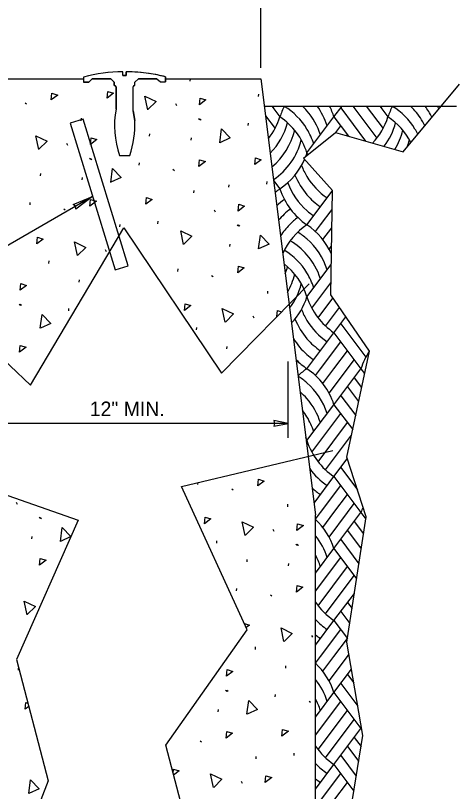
# Model space of a CAD drawing. Extents: x 99862 to 103151, y 100000 to 102076.
# Drawn here: x 102002 to 102490, y 100427 to 101282 of the extents above; entities that cross this region are included whole.
import ezdxf

# ---------------------------------------------------------------- set-up
doc = ezdxf.new("R2010")
doc.units = 0
for name, color, linetype in [('Level 15', 7, 'Continuous'), ('Level 17', 7, 'Continuous'), ('Level 20', 7, 'Continuous'), ('Level 24', 7, 'Continuous'), ('Level 25', 7, 'Continuous'), ('Level 26', 7, 'Continuous'), ('Level 6', 7, 'Continuous')]:
    doc.layers.add(name, color=color, linetype=linetype)

msp = doc.modelspace()

# ---------------------------------------------------------------- linework, layer by layer
at = {"layer": 'Level 15'}
for p, q in [((102272.15, 101223.92), (102272.15, 101307.93)), ((102087, 101082.43), (101858.43, 100950.47)), ((102302.15, 100816.59), (102302.15, 100900.59)), ((102302.15, 100832.59), (101942.15, 100832.59))]:
    msp.add_line(p, q, dxfattribs=at)
for points in [[(102087, 101082.43), (102068.72, 101068.43), (102068.15, 101071.55), (102065.74, 101073.6)], [(102302.15, 100832.59), (102286.43, 100835.67), (102287.16, 100832.59), (102286.43, 100829.5)]]:
    msp.add_lwpolyline(points, close=True, dxfattribs=at)
at = {"layer": 'Level 17'}
for p, q in [((101972.15, 101211.92), (102077.18, 101211.92)), ((102167.18, 101211.92), (102272.15, 101211.92)), ((102272.15, 101211.92), (102332.15, 100731.92)), ((102275.9, 101181.92), (102487.15, 101181.92)), ((102332.15, 100221.92), (102332.15, 100731.92))]:
    msp.add_line(p, q, dxfattribs=at)
at = {"layer": 'Level 24'}
for points in [[(102332.15, 100221.92), (102387.82, 100276.55), (102364.81, 100368.6), (102384.28, 100488.98), (102366.58, 100591.66), (102387.82, 100729.74), (102366.58, 100795.24), (102391.36, 100912.08), (102348.89, 100974.04), (102350.66, 101089.11), (102318.8, 101124.51), (102354.19, 101152.84), (102428.52, 101131.6), (102490.46, 101205.95)], [(101928.81, 100959.96), (102018.56, 100874.55), (102121.42, 101047.85), (102228.7, 100887.69), (102325.01, 100986.24)], [(101902.53, 100785.04), (102071.08, 100725.91), (102003.22, 100572.61), (102038.24, 100439.01), (102007.6, 100360.17), (102200.23, 100353.6), (102167.39, 100478.43), (102257.14, 100605.46), (102184.9, 100763.14), (102351.26, 100802.56)]]:
    msp.add_lwpolyline(points, dxfattribs=at)
at = {"layer": 'Level 25'}
for p, q in [((102284.1, 101181.92), (102293.07, 101169.97)), ((102352.46, 101169.97), (102361.43, 101181.92)), ((102359.89, 101179.87), (102387.24, 101143.39)), ((102373.2, 101181.92), (102399.63, 101146.68)), ((102388.04, 101181.92), (102406.51, 101157.3)), ((102402.89, 101181.92), (102411.86, 101169.97)), ((102277.23, 101171.28), (102287.72, 101157.3)), ((102322.77, 101130.37), (102352.46, 101169.97)), ((102352.46, 101169.97), (102368.34, 101148.79)), ((102354.42, 101152.78), (102359.89, 101160.07)), ((102280.2, 101147.52), (102280.83, 101146.68)), ((102366.65, 101149.28), (102367.31, 101150.17)), ((102286.14, 101100.01), (102293.07, 101090.77)), ((102322.77, 101051.17), (102350.64, 101088.35)), ((102337.61, 101051.17), (102350.33, 101068.13)), ((102332.07, 101043.79), (102337.61, 101051.17)), ((102340.23, 101034.86), (102350.02, 101047.92)), ((102347.12, 101024.24), (102349.71, 101027.71)), ((102322.77, 100971.98), (102349.4, 101007.49)), ((102328.11, 100959.31), (102349.09, 100987.28)), ((102335, 100948.69), (102351.33, 100970.47)), ((102343.16, 100939.77), (102358.42, 100960.13)), ((102352.46, 100932.38), (102365.51, 100949.78)), ((102359.89, 100942.28), (102387.51, 100905.45)), ((102322.77, 100892.78), (102352.46, 100932.38)), ((102352.46, 100932.38), (102382.16, 100892.78)), ((102337.61, 100892.78), (102359.89, 100922.48)), ((102352.46, 100892.78), (102367.31, 100912.58)), ((102367.31, 100892.78), (102374.74, 100902.68)), ((102332.07, 100885.39), (102337.61, 100892.78)), ((102340.23, 100876.47), (102352.46, 100892.78)), ((102347.12, 100865.85), (102367.31, 100892.78)), ((102352.46, 100853.18), (102382.16, 100892.78)), ((102382.16, 100892.78), (102386.14, 100887.48)), ((102374.74, 100882.88), (102382.87, 100872.04)), ((102367.31, 100872.98), (102379.6, 100856.61)), ((102359.89, 100863.08), (102376.32, 100841.17)), ((102322.77, 100813.59), (102352.46, 100853.18)), ((102352.46, 100853.18), (102373.05, 100825.74)), ((102328.11, 100800.92), (102359.89, 100843.29)), ((102335, 100790.3), (102367.31, 100833.39)), ((102343.16, 100781.38), (102371.72, 100819.46)), ((102352.46, 100773.99), (102367.13, 100793.55)), ((102359.89, 100783.89), (102378.16, 100759.52)), ((102330.55, 100744.77), (102352.46, 100773.99)), ((102352.46, 100773.99), (102382.16, 100734.39)), ((102337.61, 100734.39), (102359.89, 100764.09)), ((102352.46, 100734.39), (102367.31, 100754.19)), ((102367.31, 100734.39), (102374.74, 100744.29)), ((102332.15, 100727.11), (102337.61, 100734.39)), ((102340.23, 100718.08), (102352.46, 100734.39)), ((102347.12, 100707.46), (102367.31, 100734.39)), ((102352.46, 100694.79), (102382.16, 100734.39)), ((102382.16, 100734.39), (102387.45, 100727.34)), ((102374.74, 100724.49), (102384.92, 100710.91)), ((102367.31, 100714.59), (102382.4, 100694.48)), ((102359.89, 100704.69), (102379.87, 100678.05)), ((102332.15, 100667.71), (102352.46, 100694.79)), ((102352.46, 100694.79), (102377.34, 100661.62)), ((102332.15, 100647.91), (102359.89, 100684.89)), ((102335, 100631.91), (102367.31, 100674.99)), ((102343.16, 100622.98), (102374.74, 100665.09)), ((102352.46, 100615.6), (102374.86, 100645.45)), ((102374.74, 100645.3), (102374.82, 100645.19)), ((102367.31, 100635.4), (102372.29, 100628.76)), ((102359.89, 100625.5), (102369.76, 100612.33)), ((102332.15, 100588.52), (102352.46, 100615.6)), ((102352.46, 100615.6), (102367.24, 100595.9)), ((102337.61, 100576), (102359.89, 100605.7)), ((102352.46, 100576), (102367.2, 100595.64)), ((102332.15, 100568.72), (102337.61, 100576)), ((102340.23, 100559.68), (102352.46, 100576)), ((102347.12, 100549.07), (102367.31, 100576)), ((102367.31, 100576), (102368.91, 100578.13)), ((102352.46, 100536.4), (102371.69, 100562.03)), ((102367.31, 100556.2), (102374.3, 100546.88)), ((102359.89, 100546.3), (102378.73, 100521.18)), ((102332.15, 100509.32), (102352.46, 100536.4)), ((102352.46, 100536.4), (102382.16, 100496.8)), ((102332.15, 100489.52), (102359.89, 100526.5)), ((102335, 100473.52), (102367.31, 100516.6)), ((102343.16, 100464.59), (102374.74, 100506.7)), ((102352.46, 100457.2), (102382.16, 100496.8)), ((102382.16, 100496.8), (102383.16, 100495.47)), ((102374.74, 100486.9), (102382.31, 100476.81)), ((102367.31, 100477), (102379.68, 100460.52)), ((102359.89, 100467.1), (102377.04, 100444.23)), ((102332.15, 100430.12), (102352.46, 100457.2)), ((102352.46, 100457.2), (102374.41, 100427.94)), ((102337.61, 100417.61), (102359.89, 100447.31)), ((102352.46, 100417.61), (102367.31, 100437.41))]:
    msp.add_line(p, q, dxfattribs=at)
for centre, start, end in [((102357.26, 101157.09), 160.70359, 162.3566), ((102364.69, 101147.19), 152.47235, 162.3566), ((102258.57, 101117.49), 31.33163, 58.48737), ((102266, 101127.39), 40.94134, 46.52039), ((102273.42, 101137.29), 17.6434, 36.43411), ((102280.84, 101147.19), 17.6434, 27.52765), ((102476.06, 101157.09), 160.70359, 162.3566), ((102483.48, 101147.19), 152.47235, 162.3566), ((102377.36, 101117.49), 31.33163, 58.48737), ((102384.79, 101127.39), 40.94134, 46.52039), ((102392.21, 101137.29), 25.38723, 36.43411), ((102399.64, 101147.19), 24.85547, 27.52765), ((102221.45, 101192.75), 321.64092, 342.3566), ((102251.15, 101107.59), 17.6434, 56.09639), ((102265.99, 101127.39), 17.6434, 40.94141), ((102340.24, 101192.75), 316.69133, 342.3566), ((102369.94, 101107.59), 26.97043, 56.09639), ((102384.79, 101127.39), 25.91673, 40.94141), ((102228.87, 101182.85), 315.39859, 345.01126), ((102347.67, 101182.85), 322.94626, 345.01126), ((102236.3, 101172.95), 309.65405, 346.31988), ((102258.57, 101117.49), 17.6434, 31.33172), ((102355.09, 101172.95), 328.94693, 346.31988), ((102377.36, 101117.49), 26.44403, 31.33172), ((102243.72, 101163.05), 304.25669, 345.77133), ((102362.52, 101163.05), 339.69661, 345.77133), ((102251.15, 101153.15), 339.35954, 342.3566), ((102394.39, 101153.15), 197.64354, 199.34519), ((102251.15, 101153.15), 303.90361, 336.45662), ((102386.96, 101143.25), 200.87781, 211.33197), ((102379.54, 101133.35), 201.43438, 220.94161), ((102386.96, 101143.25), 211.33188, 236.09639), ((102372.11, 101123.45), 200.24322, 228.95992), ((102334.99, 101028.4), 123.90361, 128.91055), ((102364.69, 101113.55), 197.6434, 236.09639), ((102379.54, 101133.35), 220.94154, 236.09639), ((102342.41, 101018.5), 126.30625, 134.60118), ((102349.84, 101008.6), 127.1006, 140.76474), ((102357.26, 100998.7), 126.331, 135.71278), ((102372.11, 101123.45), 228.95986, 236.09639), ((102357.26, 100998.7), 135.71269, 147.64184), ((102364.69, 100988.8), 123.90361, 155.71959), ((102280.84, 100988.8), 23.85276, 56.09634), ((102273.42, 100978.9), 48.95968, 58.54646), ((102266, 100969), 40.94134, 59.30215), ((102273.42, 100978.9), 17.6434, 48.95975), ((102258.57, 100959.1), 31.33163, 58.48737), ((102265.99, 100969), 17.6434, 40.94141), ((102251.15, 100949.2), 17.6434, 51.81332), ((102228.87, 101024.46), 338.86712, 345.01126), ((102236.3, 101014.56), 330.17264, 346.31988), ((102258.57, 100959.1), 17.6434, 31.33172), ((102243.72, 101004.66), 322.96898, 345.77133), ((102251.15, 100994.76), 316.60104, 342.3566), ((102394.39, 100994.76), 197.64354, 236.09639), ((102386.96, 100984.86), 200.87781, 211.33197), ((102379.54, 100974.96), 201.43438, 220.94161), ((102386.96, 100984.86), 211.33188, 236.09639), ((102372.11, 100965.06), 211.29269, 228.95992), ((102379.54, 100974.96), 220.94154, 236.09639), ((102372.11, 100965.06), 228.95986, 236.09639), ((102453.78, 100870), 146.25564, 162.3566), ((102364.69, 100955.16), 224.18689, 236.09639), ((102357.26, 100840.31), 126.331, 127.8157), ((102364.69, 100830.41), 123.90361, 133.43069), ((102280.84, 100830.41), 17.6434, 56.09634), ((102273.42, 100820.51), 48.95968, 58.12998), ((102273.42, 100820.51), 17.6434, 48.95975), ((102266, 100810.61), 40.94134, 49.08438), ((102265.99, 100810.61), 17.6434, 40.94141), ((102258.57, 100800.71), 31.33163, 38.03389), ((102258.57, 100800.71), 17.6434, 31.33172), ((102251.15, 100790.81), 17.6434, 20.62953), ((102251.15, 100836.37), 340.91273, 342.3566), ((102394.39, 100836.37), 197.64354, 236.09639), ((102386.96, 100826.47), 215.5249, 236.09639), ((102379.54, 100816.57), 227.19281, 236.09639), ((102453.78, 100711.61), 157.47358, 162.3566), ((102280.84, 100672.01), 17.6434, 46.94368), ((102273.42, 100662.11), 17.6434, 38.60116), ((102265.99, 100652.21), 17.6434, 28.32156), ((102394.39, 100677.97), 214.10189, 236.09639), ((102386.96, 100668.07), 223.17637, 236.09639), ((102379.54, 100658.17), 230.91594, 236.09639), ((102280.84, 100513.62), 17.6434, 46.94368), ((102273.42, 100503.72), 17.6434, 38.60116), ((102265.99, 100493.82), 17.6434, 28.32156), ((102340.24, 100559.18), 303.90361, 304.53819), ((102394.39, 100519.58), 214.10189, 236.09639), ((102386.96, 100509.68), 223.17637, 236.09639), ((102379.54, 100499.78), 230.91594, 236.09639)]:
    msp.add_arc(centre, 75.15, start, end, dxfattribs=at)
at = {"layer": 'Level 26'}
for p, q in [((102194.45, 101209.4), (102194.62, 101211.92)), ((102269.59, 101192.23), (102269.77, 101194.85)), ((102012.89, 101185.55), (102014.44, 101184.42)), ((102178.13, 101184.71), (102179.2, 101182.55)), ((102074.53, 101165.75), (102074.71, 101168.37)), ((102203.49, 101168.18), (102205.04, 101167.04)), ((102204.7, 101167.97), (102206.25, 101166.83)), ((102258.16, 101160.54), (102258.34, 101163.16)), ((102149.67, 101148.59), (102149.85, 101151.21)), ((102195.48, 101144.24), (102195.66, 101146.86)), ((102058.21, 101141.06), (102059.28, 101138.9)), ((102083.58, 101124.53), (102085.13, 101123.39)), ((102084.79, 101124.33), (102086.34, 101123.19)), ((102138.24, 101116.89), (102138.42, 101119.51)), ((102175.37, 101112.26), (102176.91, 101111.12)), ((102029.75, 101104.94), (102029.94, 101107.56)), ((102075.56, 101100.6), (102075.74, 101103.22)), ((102237.01, 101092.46), (102237.19, 101095.07)), ((102278.8, 101096.04), (102278.98, 101098.66)), ((102198.37, 101086.49), (102198.55, 101089.11)), ((102018.33, 101073.25), (102018.51, 101075.86)), ((102055.45, 101068.62), (102057, 101067.48)), ((102220.69, 101067.77), (102221.76, 101065.61)), ((102117.1, 101048.81), (102117.28, 101051.43)), ((102158.88, 101052.4), (102159.06, 101055.01)), ((102246.06, 101051.24), (102247.61, 101050.1)), ((102247.27, 101051.03), (102248.82, 101049.89)), ((102238.04, 101027.31), (102238.22, 101029.92)), ((102100.77, 101024.12), (102101.84, 101021.96)), ((102038.97, 101008.75), (102039.15, 101011.37)), ((102180.81, 100999.95), (102180.99, 101002.57)), ((102072.32, 100988), (102072.5, 100990.62)), ((102217.93, 100995.32), (102219.48, 100994.18)), ((102279.57, 100975.52), (102279.76, 100978.13)), ((102006.22, 100963.95), (102007.77, 100962.81)), ((102007.43, 100963.74), (102008.98, 100962.6)), ((102060.89, 100956.31), (102061.07, 100958.93)), ((102263.25, 100950.83), (102264.32, 100948.67)), ((102201.45, 100935.46), (102201.63, 100938.07)), ((102234.8, 100914.71), (102234.98, 100917.33)), ((102202.83, 100765.32), (102202.98, 100767.42)), ((102239.96, 100760.69), (102241.51, 100759.55)), ((102002.89, 100745.85), (102003.96, 100743.68)), ((102301.6, 100740.88), (102301.79, 100743.5)), ((102028.25, 100729.31), (102029.8, 100728.18)), ((102029.46, 100729.11), (102031.01, 100727.97)), ((102285.28, 100716.2), (102286.35, 100714.04)), ((102020.24, 100705.38), (102020.42, 100708)), ((102223.47, 100700.82), (102223.66, 100703.44)), ((102310.65, 100699.67), (102312.2, 100698.53)), ((102311.86, 100699.46), (102313.41, 100698.32)), ((102256.82, 100680.08), (102257.01, 100682.69)), ((102302.63, 100675.73), (102302.81, 100678.35)), ((102245.4, 100648.38), (102245.58, 100651)), ((102282.52, 100643.75), (102284.07, 100642.61)), ((102327.84, 100599.26), (102328.91, 100597.1)), ((102266.04, 100583.88), (102266.22, 100586.5)), ((102005.56, 100561.09), (102005.7, 100563.13)), ((102299.39, 100563.14), (102299.57, 100565.75)), ((102233.3, 100539.08), (102234.84, 100537.94)), ((102234.5, 100538.88), (102236.05, 100537.74)), ((102287.96, 100531.44), (102288.14, 100534.06)), ((102325.08, 100526.81), (102326.63, 100525.67)), ((102225.28, 100515.15), (102225.46, 100517.77)), ((102205.17, 100483.16), (102206.71, 100482.03)), ((102308.6, 100466.94), (102308.78, 100469.56)), ((102266.81, 100463.36), (102266.99, 100465.98)), ((102250.49, 100438.67), (102251.56, 100436.51))]:
    msp.add_line(p, q, dxfattribs=at)
for points in [[(102041.54, 101188.61), (102042.27, 101195.96), (102048.64, 101194.03), (102041.54, 101188.61)], [(102102.93, 101190.69), (102103.66, 101198.04), (102110.03, 101196.11), (102102.93, 101190.69)], [(102147.72, 101177.83), (102144.5, 101192.86), (102156.83, 101186.87), (102147.92, 101178)], [(102204.52, 101183.29), (102205.24, 101190.64), (102211.62, 101188.71), (102204.52, 101183.29)], [(102226.82, 101141.48), (102228.94, 101156.71), (102238.48, 101146.86), (102227.07, 101141.57)], [(102027.8, 101134.18), (102024.58, 101149.21), (102036.91, 101143.22), (102028.01, 101134.35)], [(102084.6, 101139.65), (102085.33, 101147), (102091.7, 101145.07), (102084.6, 101139.65)], [(102204.02, 101115.32), (102204.75, 101122.67), (102211.12, 101120.74), (102204.02, 101115.32)], [(102265.41, 101117.4), (102266.14, 101124.75), (102272.51, 101122.82), (102265.41, 101117.4)], [(102106.91, 101097.83), (102109.02, 101113.06), (102118.56, 101103.21), (102107.16, 101097.92)], [(102084.1, 101071.67), (102084.83, 101079.03), (102091.2, 101077.09), (102084.1, 101071.67)], [(102145.5, 101073.75), (102146.22, 101081.1), (102152.59, 101079.17), (102145.5, 101073.75)], [(102247.08, 101066.35), (102247.81, 101073.71), (102254.18, 101071.77), (102247.08, 101066.35)], [(102187.11, 101029.6), (102183.89, 101044.63), (102196.23, 101038.64), (102187.32, 101029.77)], [(102025.58, 101030.11), (102026.3, 101037.46), (102032.68, 101035.52), (102025.58, 101030.11)], [(102269.39, 101024.54), (102271.5, 101039.77), (102281.04, 101029.92), (102269.64, 101024.63)], [(102070.36, 101017.24), (102067.14, 101032.28), (102079.48, 101026.28), (102070.57, 101017.42)], [(102246.58, 100998.38), (102247.31, 101005.73), (102253.68, 101003.8), (102246.58, 100998.38)], [(102007.25, 100979.06), (102007.97, 100986.41), (102014.35, 100984.48), (102007.25, 100979.06)], [(102188.06, 100956.81), (102188.78, 100964.16), (102195.16, 100962.23), (102188.06, 100956.81)], [(102232.84, 100943.95), (102229.62, 100958.98), (102241.95, 100952.99), (102233.05, 100944.12)], [(102289.71, 100950.12), (102290.37, 100956.77), (102294.87, 100955.4)], [(102029.55, 100937.25), (102031.67, 100952.48), (102041.21, 100942.62), (102029.8, 100937.34)], [(102006.75, 100911.09), (102007.48, 100918.44), (102013.85, 100916.51), (102006.75, 100911.09)], [(102268.61, 100763.75), (102269.34, 100771.1), (102275.71, 100769.17), (102268.61, 100763.75)], [(102210.09, 100722.18), (102210.81, 100729.53), (102217.19, 100727.6), (102210.09, 100722.18)], [(102051.58, 100702.62), (102053.69, 100717.84), (102063.17, 100708.05)], [(102254.87, 100709.32), (102251.65, 100724.35), (102263.98, 100718.35), (102255.08, 100709.49)], [(102311.67, 100714.78), (102312.4, 100722.13), (102318.77, 100720.2), (102311.67, 100714.78)], [(102063.12, 100707.94), (102051.83, 100702.71)], [(102028.78, 100676.45), (102029.51, 100683.81), (102035.88, 100681.87), (102028.78, 100676.45)], [(102311.18, 100646.81), (102311.9, 100654.16), (102318.27, 100652.23), (102311.18, 100646.81)], [(102015.04, 100622.03), (102011.82, 100637.06), (102024.15, 100631.06), (102015.24, 100622.2)], [(102253.95, 100612.42), (102259.75, 100610.66), (102256.05, 100607.84)], [(102297.44, 100592.38), (102294.21, 100607.41), (102306.55, 100601.41), (102297.64, 100592.55)], [(102234.32, 100554.2), (102235.04, 100561.55), (102241.42, 100559.61), (102234.32, 100554.2)], [(102012.82, 100517.95), (102013.54, 100525.3), (102015.8, 100524.62)], [(102016.76, 100520.96), (102012.82, 100517.95)], [(102256.62, 100512.38), (102258.74, 100527.61), (102268.28, 100517.76), (102256.87, 100512.47)], [(102295.21, 100488.3), (102295.94, 100495.65), (102302.31, 100493.72), (102295.21, 100488.3)], [(102233.82, 100486.22), (102234.55, 100493.57), (102240.92, 100491.64), (102233.82, 100486.22)], [(102175.56, 100447.37), (102176.02, 100452.01), (102182.39, 100450.07), (102176.11, 100445.28)], [(102220.08, 100431.79), (102216.86, 100446.82), (102229.19, 100440.83), (102220.28, 100431.96)], [(102276.88, 100437.26), (102277.61, 100444.61), (102283.98, 100442.67), (102276.88, 100437.26)], [(102016.79, 100425.09), (102018.9, 100440.32), (102028.44, 100430.47), (102017.04, 100425.18)]]:
    msp.add_lwpolyline(points, dxfattribs=at)
at = {"layer": 'Level 6'}
for p, q in [((102077.18, 101213.8), (102077.18, 101208.18)), ((102077.18, 101213.8), (102077.18, 101208.18)), ((102077.18, 101213.8), (102077.18, 101208.18)), ((102120.31, 101215.62), (102120.31, 101219.62)), ((102120.31, 101215.62), (102120.31, 101219.62)), ((102120.31, 101215.62), (102120.31, 101219.62)), ((102120.31, 101215.62), (102124.06, 101215.62)), ((102120.31, 101215.62), (102124.06, 101215.62)), ((102124.06, 101215.62), (102120.31, 101215.62)), ((102124.06, 101215.62), (102124.06, 101219.62)), ((102124.06, 101215.62), (102124.06, 101219.62)), ((102124.06, 101219.62), (102124.06, 101215.62)), ((102167.18, 101214.06), (102167.18, 101208.42)), ((102167.18, 101214.06), (102167.18, 101208.42)), ((102167.18, 101208.42), (102167.18, 101214.05)), ((102082.8, 101208.18), (102077.18, 101208.18)), ((102082.8, 101208.18), (102077.18, 101208.18)), ((102077.18, 101208.18), (102082.8, 101208.18)), ((102086.53, 101211.93), (102082.8, 101208.18)), ((102086.53, 101211.93), (102082.8, 101208.18)), ((102082.8, 101208.18), (102086.53, 101211.93)), ((102107.15, 101211.93), (102086.53, 101211.93)), ((102107.15, 101211.93), (102086.53, 101211.93)), ((102086.53, 101211.93), (102107.15, 101211.93)), ((102107.15, 101211.93), (102110.91, 101208.18)), ((102107.15, 101211.93), (102110.91, 101208.18)), ((102107.15, 101211.93), (102110.91, 101208.18)), ((102110.91, 101204.43), (102110.91, 101208.18)), ((102110.91, 101208.18), (102110.91, 101204.43)), ((102111.28, 101204.43), (102110.91, 101204.43)), ((102110.91, 101204.43), (102111.28, 101204.43)), ((102133.42, 101204.43), (102133.04, 101204.43)), ((102133.42, 101204.43), (102133.04, 101204.43)), ((102133.04, 101204.43), (102133.42, 101204.43)), ((102137.43, 101211.93), (102133.42, 101208.18)), ((102137.43, 101211.93), (102133.42, 101208.18)), ((102133.42, 101208.18), (102137.43, 101211.93)), ((102133.42, 101204.43), (102133.42, 101208.18)), ((102133.42, 101204.43), (102133.42, 101208.18)), ((102157.79, 101211.93), (102137.43, 101211.93)), ((102157.79, 101211.93), (102137.43, 101211.93)), ((102137.43, 101211.93), (102157.79, 101211.93)), ((102157.79, 101211.93), (102161.56, 101208.42)), ((102157.79, 101211.93), (102161.56, 101208.42)), ((102157.79, 101211.93), (102161.56, 101208.42)), ((102161.56, 101208.42), (102167.18, 101208.42)), ((102161.56, 101208.42), (102167.18, 101208.42)), ((102161.56, 101208.42), (102167.18, 101208.42)), ((102112.8, 101202.94), (102112.8, 101202.55)), ((102112.8, 101202.94), (102112.8, 101202.55)), ((102112.8, 101181.94), (102112.8, 101202.52)), ((102112.8, 101202.52), (102112.8, 101181.94)), ((102131.54, 101181.94), (102131.54, 101202.93)), ((102131.54, 101181.94), (102131.54, 101202.93)), ((102112.8, 101178.57), (102112.8, 101181.94)), ((102112.8, 101181.94), (102112.8, 101178.57)), ((102112.8, 101178.57), (102112.8, 101178.57)), ((102131.54, 101176.68), (102131.54, 101181.94)), ((102131.54, 101176.68), (102131.54, 101181.94)), ((102131.54, 101176.68), (102133.42, 101166.07)), ((102133.42, 101166.07), (102131.54, 101176.68)), ((102116.52, 101127.45), (102127.8, 101127.45)), ((102116.53, 101127.45), (102127.81, 101127.45))]:
    msp.add_line(p, q, dxfattribs=at)
msp.add_lwpolyline([(102111.74, 101001.66), (102126.09, 101006.06), (102076.61, 101167.6), (102062.26, 101163.2)], close=True, dxfattribs=at)
for centre, radius, start, end in [((102122.64, 101039.59), 180.06, 90.74606, 104.63167), ((102122.64, 101039.59), 180.06, 90.74606, 104.63167), ((102122.64, 101039.59), 180.06, 90.74606, 104.62391), ((102122.64, 101039.59), 180.06, 75.67654, 89.55237), ((102122.64, 101039.59), 180.06, 81.52685, 89.54672), ((102122.64, 101039.59), 180.06, 75.67654, 81.52685), ((102122.64, 101039.59), 180.06, 75.67721, 81.52685), ((102111.29, 101202.94), 1.5, 0, 90), ((102111.29, 101202.94), 1.5, 0.17334, 90), ((102133.05, 101202.94), 1.5, 90, 180), ((102133.05, 101202.94), 1.5, 90.23946, 180), ((102212.69, 101160.2), 101.56, 169.57783, 198.80573), ((102212.69, 101160.2), 101.56, 169.57783, 198.80573), ((102034.47, 101160.78), 99.1, 340.35429, 3.06618), ((102034.47, 101160.78), 99.1, 340.35429, 3.0604)]:
    msp.add_arc(centre, radius, start, end, dxfattribs=at)

# ---------------------------------------------------------------- texts
at = {"layer": 'Level 20'}
msp.add_text('12" MIN.', height=16, dxfattribs=at).set_placement((102083.87, 100840.59))

doc.saveas('drawing.dxf')
